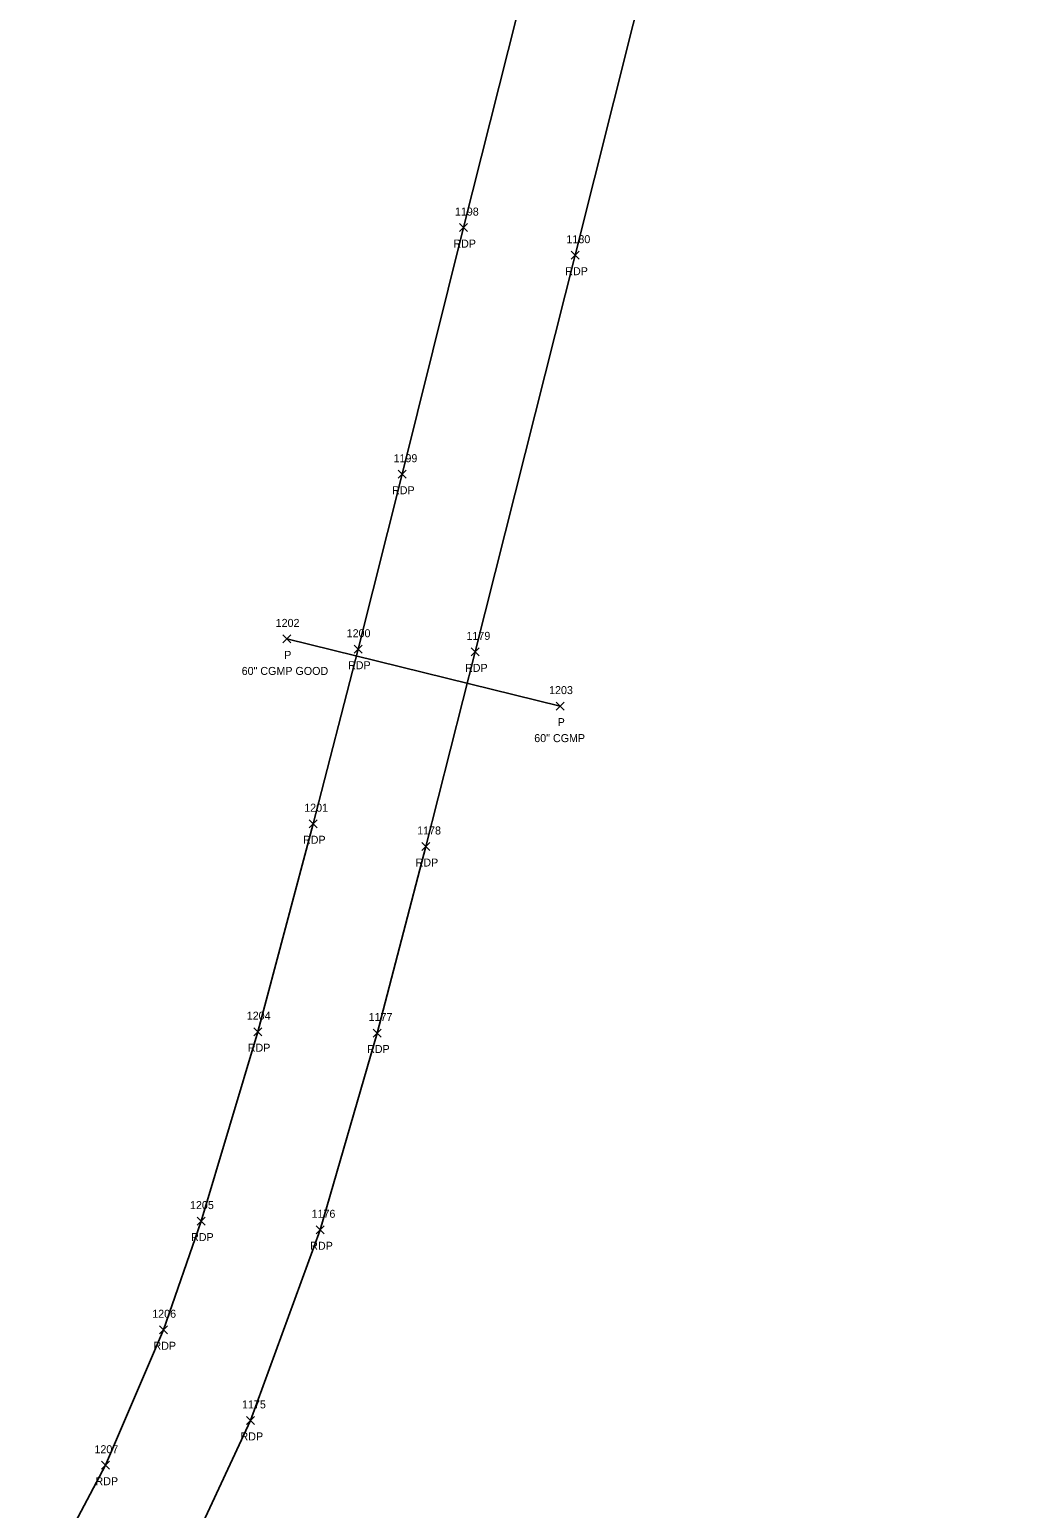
# Model space of a CAD drawing. Extents: x 1496556 to 1498241, y 599216 to 604470.
# Drawn here: x 1497984.6 to 1498234, y 603730.8 to 604100.3 of the extents above; entities that cross this region are included whole.
import ezdxf

# ---------------------------------------------------------------- set-up
doc = ezdxf.new("R2010")
doc.units = 0
for name, color, linetype in [('D_A', 7, 'Continuous'), ('D_C', 7, 'Continuous'), ('D_I', 7, 'Continuous'), ('D_TIC', 7, 'Continuous'), ('DCP', 7, 'Continuous'), ('P_A', 7, 'Continuous'), ('P_I', 7, 'Continuous'), ('P_TIC', 7, 'Continuous'), ('PET', 7, 'Continuous')]:
    doc.layers.add(name, color=color, linetype=linetype)

msp = doc.modelspace()

# ---------------------------------------------------------------- linework, layer by layer
at = {"layer": 'D_TIC'}
for points in [[(1498047.79, 603947.07), (1498049.79, 603949.07)], [(1498049.79, 603947.07), (1498047.79, 603949.07)], [(1498116.07, 603930.28), (1498118.07, 603932.28)], [(1498118.07, 603930.28), (1498116.07, 603932.28)]]:
    msp.add_lwpolyline(points, dxfattribs=at)
at = {"layer": 'DCP'}
msp.add_lwpolyline([(1498048.79, 603948.07), (1498117.07, 603931.28)], dxfattribs=at)
at = {"layer": 'P_TIC'}
for points in [[(1498091.91, 604049.85), (1498093.91, 604051.85)], [(1498093.91, 604049.85), (1498091.91, 604051.85)], [(1498119.84, 604042.96), (1498121.84, 604044.96)], [(1498121.84, 604042.96), (1498119.84, 604044.96)], [(1498076.58, 603988.22), (1498078.58, 603990.22)], [(1498078.58, 603988.22), (1498076.58, 603990.22)], [(1498065.61, 603944.49), (1498067.61, 603946.49)], [(1498067.61, 603944.49), (1498065.61, 603946.49)], [(1498094.81, 603943.84), (1498096.81, 603945.84)], [(1498096.81, 603943.84), (1498094.81, 603945.84)], [(1498054.36, 603900.89), (1498056.36, 603902.89)], [(1498056.36, 603900.89), (1498054.36, 603902.89)], [(1498082.48, 603895.2), (1498084.48, 603897.2)], [(1498084.48, 603895.2), (1498082.48, 603897.2)], [(1498040.58, 603848.92), (1498042.58, 603850.92)], [(1498042.58, 603848.92), (1498040.58, 603850.92)], [(1498070.36, 603848.59), (1498072.36, 603850.59)], [(1498072.36, 603848.59), (1498070.36, 603850.59)], [(1498026.4, 603801.6), (1498028.4, 603803.6)], [(1498028.4, 603801.6), (1498026.4, 603803.6)], [(1498056.17, 603799.42), (1498058.17, 603801.42)], [(1498058.17, 603799.42), (1498056.17, 603801.42)], [(1498017.02, 603774.44), (1498019.02, 603776.44)], [(1498019.02, 603774.44), (1498017.02, 603776.44)], [(1498038.75, 603751.79), (1498040.75, 603753.79)], [(1498040.75, 603751.79), (1498038.75, 603753.79)], [(1498002.54, 603740.59), (1498004.54, 603742.59)], [(1498004.54, 603740.59), (1498002.54, 603742.59)]]:
    msp.add_lwpolyline(points, dxfattribs=at)
at = {"layer": 'PET'}
for points in [[(1498208.59, 604464.85), (1498189.82, 604420.08), (1498176, 604378.05), (1498167.5, 604348.18), (1498147, 604267.63), (1498131.48, 604205.54), (1498117.5, 604148.32), (1498092.91, 604050.85), (1498077.58, 603989.22), (1498066.61, 603945.49), (1498055.36, 603901.89), (1498041.58, 603849.92), (1498027.4, 603802.6), (1498018.02, 603775.44), (1498003.54, 603741.59), (1497984.58, 603705.71)], [(1498024.5, 603720), (1498039.75, 603752.79), (1498057.17, 603800.42), (1498071.36, 603849.59), (1498083.48, 603896.2), (1498095.81, 603944.84), (1498120.84, 604043.96), (1498144.93, 604140.23), (1498166.67, 604228.45), (1498179.41, 604280.18), (1498191.68, 604326.66), (1498203.39, 604369.21), (1498215.73, 604409.1), (1498233.98, 604454.06)]]:
    msp.add_lwpolyline(points, dxfattribs=at)

# ---------------------------------------------------------------- texts
at = {"layer": 'D_A'}
for p in [(1498048.17, 603943.07), (1498116.44, 603926.28)]:
    msp.add_text('P', height=2, dxfattribs=at).set_placement(p)
at = {"layer": 'D_C'}
for s, p in [('60" CGMP GOOD', (1498037.53, 603939.07)), ('60" CGMP', (1498110.59, 603922.28))]:
    msp.add_text(s, height=2, dxfattribs=at).set_placement(p)
at = {"layer": 'D_I'}
for s, p in [('1202', (1498046.02, 603951.07)), ('1203', (1498114.29, 603934.28))]:
    msp.add_text(s, height=2, dxfattribs=at).set_placement(p)
at = {"layer": 'P_A'}
for p in [(1498090.39, 604045.85), (1498118.33, 604038.96), (1498075.07, 603984.22), (1498064.09, 603940.49), (1498093.3, 603939.84), (1498052.84, 603896.89), (1498080.96, 603891.2), (1498039.06, 603844.92), (1498068.85, 603844.59), (1498024.89, 603797.6), (1498054.65, 603795.42), (1498015.51, 603770.44), (1498037.24, 603747.79), (1498001.03, 603736.59)]:
    msp.add_text('RDP', height=2, dxfattribs=at).set_placement(p)
at = {"layer": 'P_I'}
for s, p in [('1198', (1498090.78, 604053.85)), ('1180', (1498118.63, 604046.96)), ('1199', (1498075.45, 603992.22)), ('1200', (1498063.75, 603948.49)), ('1179', (1498093.67, 603947.84)), ('1201', (1498053.15, 603904.89)), ('1178', (1498081.35, 603899.2)), ('1204', (1498038.8, 603852.92)), ('1177', (1498069.23, 603852.59)), ('1205', (1498024.63, 603805.6)), ('1176', (1498054.98, 603803.42)), ('1206', (1498015.2, 603778.44)), ('1175', (1498037.62, 603755.79)), ('1207', (1498000.77, 603744.59))]:
    msp.add_text(s, height=2, dxfattribs=at).set_placement(p)

doc.saveas('drawing.dxf')
